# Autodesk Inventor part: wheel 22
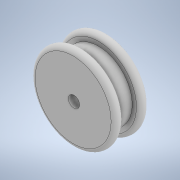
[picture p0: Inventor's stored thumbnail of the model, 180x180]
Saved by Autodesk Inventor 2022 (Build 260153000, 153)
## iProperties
Created: 2021-07
Part Number: wheel 22
Material: Generic
Document SubType Name: Modeling
Designer: Avani Patil
Density: 1 g/cm^3
Appearance: Default
Author: Avani Patil
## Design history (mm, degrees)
sketch "Sketch1"
  geometry: L1 (60, -15)-(75, -15); L2 (75, -15)-(75, -30); L3 (75, -30)-(0, -30); L4 (0, -30)-(0, 30); L5 (0, 30)-(75, 30); L6 (75, 30)-(75, 15); L7 (75, 15)-(60, 15); L8 (60, 15)-(60, -15); 1 further point
  constraints: 16 end point, 3 perpendicular, 2 point on line, 1 vertical
revolve "Revolution1" sketch "Sketch1" stored, may be unused: angle "d12" = 90 deg
sketch "Sketch2"
  geometry: 2 further points
hole "Hole1" sketch "Sketch2" at (-1.571, -2.143) diameter "d13" = 20; stored, may be unused: countersink angle "d17" = 82 deg, drill point angle "d19" = 118 deg; dims "d14" = 19.05, "d15" = 9.525, "d16" = 6.35, "d18" = 25.4
feature "Full Round Fillet1"
feature "Full Round Fillet2"
body "Solid1"
